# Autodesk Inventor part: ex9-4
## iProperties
Created: 2006-03
Part Number: ex9-4
Document SubType Name: Sheet Metal
Designer: Elise Moss
Author: Elise Moss
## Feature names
1. Plate1
2. Bend1
3. Plate2
4. Bend2
5. Cut1
